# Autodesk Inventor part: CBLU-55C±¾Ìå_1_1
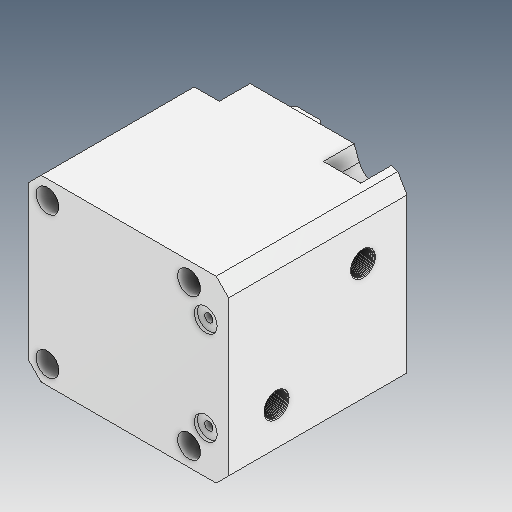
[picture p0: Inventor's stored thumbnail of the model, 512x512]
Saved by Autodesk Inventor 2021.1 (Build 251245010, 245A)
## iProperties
Created: 2021-05
Part Number: CBLU-55C±¾Ìå_1_1
Material: Ogólny
Document SubType Name: Modeling
Designer: user
Density: 1 g/cm^3
Appearance: Domyślna
Author: user
Revision Number: ÈÎºÎ
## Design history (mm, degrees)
feature "ÊäÈë1"
feature "ÊäÈë2"
feature "ÊäÈë3"
feature "ÇÐ³ý-À­Éì1" [ÊäÈë]
node "Bryła1"
node "Bryła2"
node "Bryła3"
node "Bryła4"
